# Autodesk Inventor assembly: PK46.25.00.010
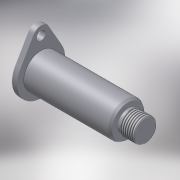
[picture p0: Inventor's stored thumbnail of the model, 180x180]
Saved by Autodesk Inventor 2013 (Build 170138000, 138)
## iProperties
Created: 2005-05
Part Number: PK46.25.00.010
Document SubType Name: Assembly
Designer: PVitaliy
Manufacturer: Standard
Standards Organization: Custom
Author: PVitaliy
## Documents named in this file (3)
- C:\Product Design Suite 2013 Test Drive\Dynamic Simulation\Workspace\Assy, Chassis, Front\PK46.25.00.010.iam
- C:\Product Design Suite 2013 Test Drive\Dynamic Simulation\Workspace\Assy, Chassis, Front\PK46.25.00.001.ipt
- C:\Product Design Suite 2013 Test Drive\Dynamic Simulation\Workspace\Assy, Chassis, Front\PK46.25.00.002.ipt
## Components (2 placed, 2 different names)
1. PK46.25.00.001:1 — Вставка:1
2. PK46.25.00.002:1 — Вставка:1, Совмещение:1
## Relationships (2: Insert 1, Mate 1)
- Вставка:1 [Insert]: PK46.25.00.001:1 ↔ PK46.25.00.002:1
- Совмещение:1 [Mate]: PK46.25.00.002:1
